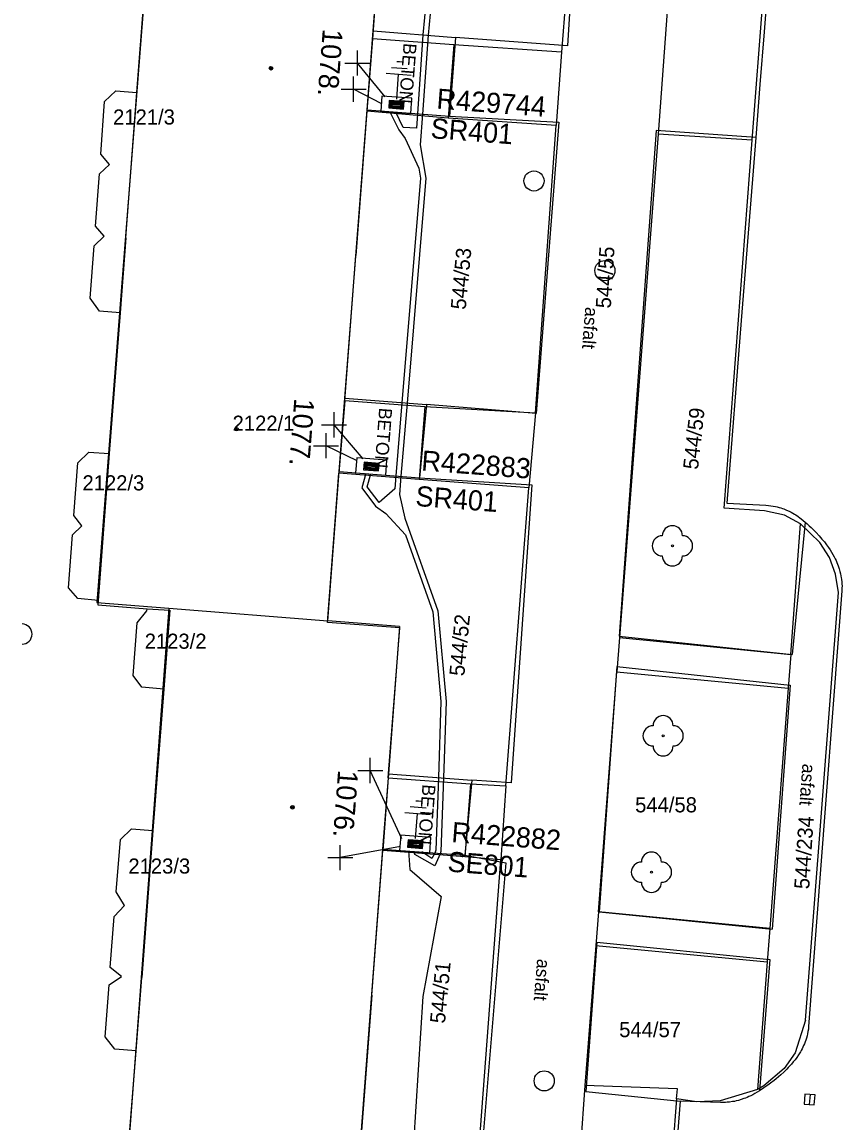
# Model space of a CAD drawing. Extents: x -540150 to -533593, y -1185082 to -1180066.
# Drawn here: x -536258 to -536217.3, y -1184423.9 to -1184369.3 of the extents above; entities that cross this region are included whole.
import ezdxf

# ---------------------------------------------------------------- set-up
doc = ezdxf.new("R2010")
doc.units = 0
for name, color, linetype in [('KN_HRAN_PARCEL', 7, 'Continuous'), ('KN_PARC_Č', 7, 'Continuous'), ('KN_VKP_HRAN_', 7, 'Continuous'), ('Vrstva 1', 7, 'Continuous'), ('Vrstva 10', 7, 'Continuous'), ('Vrstva 11', 7, 'Continuous'), ('Vrstva 14', 7, 'Continuous'), ('Vrstva 15', 7, 'Continuous'), ('Vrstva 22', 7, 'Continuous'), ('Vrstva 27', 7, 'Continuous'), ('Vrstva 28', 7, 'Continuous'), ('Vrstva 29', 7, 'Continuous'), ('Vrstva 30', 7, 'Continuous'), ('Vrstva 34', 7, 'Continuous'), ('Vrstva 39', 7, 'Continuous'), ('Vrstva 40', 7, 'Continuous'), ('Vrstva 47', 7, 'Continuous'), ('Vrstva 5', 7, 'Continuous'), ('Vrstva 59', 7, 'Continuous'), ('Vrstva 8', 7, 'Continuous')]:
    doc.layers.add(name, color=color, linetype=linetype)

# ---------------------------------------------------------------- blocks, each defined once
blk = doc.blocks.new('NN800')
at = {"layer": 'Vrstva 1'}
for points in [[(-0.442, 0.442), (0.442, -0.442)], [(-0.442, -0.442), (0.442, 0.442)]]:
    blk.add_lwpolyline(points, dxfattribs=at)
blk = doc.blocks.new('NN620')
at = {"layer": 'Vrstva 8'}
for points in [[(0.752, 0.004), (-0.748, 0.004)], [(-0.748, 0.004), (-0.748, -0.746)], [(0.752, -0.746), (0.752, 0.004)], [(0.368, -0.18), (-0.376, -0.18)], [(-0.376, -0.18), (-0.376, -0.558)], [(0.321, -0.227), (-0.329, -0.227)], [(-0.329, -0.227), (-0.329, -0.51)], [(-0.329, -0.51), (0.321, -0.51)], [(0.274, -0.274), (-0.281, -0.274)], [(-0.281, -0.274), (-0.281, -0.463)], [(-0.281, -0.463), (0.274, -0.463)], [(0.227, -0.321), (-0.234, -0.321)], [(-0.234, -0.321), (-0.234, -0.416)], [(-0.234, -0.416), (0.227, -0.416)], [(-0.193, -0.369), (0.185, -0.369)], [(0.227, -0.416), (0.227, -0.321)], [(0.274, -0.463), (0.274, -0.274)], [(0.321, -0.51), (0.321, -0.227)], [(0.368, -0.558), (0.368, -0.18)], [(-0.748, -0.746), (0.752, -0.746)], [(-0.376, -0.558), (0.368, -0.558)]]:
    blk.add_lwpolyline(points, dxfattribs=at)
blk = doc.blocks.new('NN810')
at = {"layer": 'Vrstva 14'}
for points in [[(0.004, -0.64), (0.004, -1.89)], [(0.629, -1.89), (-0.621, -1.89)], [(0.388, -2.2), (-0.399, -2.2)], [(0.004, -2.515), (-0.124, -2.515)], [(0.137, -2.515), (0.004, -2.515)]]:
    blk.add_lwpolyline(points, dxfattribs=at)

msp = doc.modelspace()

# ---------------------------------------------------------------- linework, layer by layer
at = {"layer": 'KN_HRAN_PARCEL'}
for p, q in [((-536230.131, -1184356.565), (-536231.231, -1184370.805)), ((-536240.071, -1184362.975), (-536240.621, -1184370.155)), ((-536252.311, -1184372.815), (-536251.771, -1184365.815)), ((-536221.771, -1184375.185), (-536221.221, -1184367.975)), ((-536236.581, -1184370.445), (-536240.621, -1184370.155)), ((-536231.231, -1184370.805), (-536236.581, -1184370.445)), ((-536231.231, -1184370.805), (-536231.501, -1184374.445)), ((-536253.911, -1184373.255), (-536253.361, -1184372.735)), ((-536253.361, -1184372.735), (-536252.311, -1184372.815)), ((-536252.861, -1184380.025), (-536252.311, -1184372.815)), ((-536254.101, -1184375.875), (-536253.911, -1184373.255)), ((-536240.891, -1184373.745), (-536241.441, -1184380.905)), ((-536236.861, -1184374.085), (-536240.891, -1184373.745)), ((-536231.501, -1184374.445), (-536236.861, -1184374.085)), ((-536232.521, -1184388.715), (-536231.501, -1184374.445)), ((-536226.441, -1184374.875), (-536228.361, -1184399.865)), ((-536221.771, -1184375.185), (-536226.441, -1184374.875)), ((-536223.161, -1184393.445), (-536221.771, -1184375.185)), ((-536253.661, -1184376.385), (-536254.101, -1184375.875)), ((-536254.361, -1184379.455), (-536254.161, -1184376.845)), ((-536254.161, -1184376.845), (-536253.661, -1184376.385)), ((-536253.941, -1184379.945), (-536254.361, -1184379.455)), ((-536254.431, -1184380.425), (-536253.941, -1184379.945)), ((-536252.861, -1184380.025), (-536253.141, -1184383.745)), ((-536254.631, -1184383.025), (-536254.431, -1184380.425)), ((-536241.991, -1184388.105), (-536241.441, -1184380.905)), ((-536254.171, -1184383.665), (-536254.631, -1184383.025)), ((-536253.141, -1184383.745), (-536254.171, -1184383.665)), ((-536253.141, -1184383.745), (-536253.681, -1184390.735)), ((-536241.991, -1184388.105), (-536238.011, -1184388.405)), ((-536238.011, -1184388.405), (-536232.521, -1184388.715)), ((-536232.521, -1184388.715), (-536232.861, -1184392.445)), ((-536255.241, -1184391.195), (-536254.701, -1184390.665)), ((-536254.701, -1184390.665), (-536253.681, -1184390.735)), ((-536253.681, -1184390.735), (-536254.231, -1184398.025)), ((-536255.441, -1184393.815), (-536255.241, -1184391.195)), ((-536242.841, -1184399.125), (-536242.281, -1184391.715)), ((-536238.291, -1184392.025), (-536242.281, -1184391.715)), ((-536232.861, -1184392.445), (-536238.291, -1184392.025)), ((-536233.991, -1184407.225), (-536232.861, -1184392.445)), ((-536221.161, -1184393.575), (-536223.161, -1184393.445)), ((-536220.161, -1184393.795), (-536221.161, -1184393.575)), ((-536255.511, -1184394.775), (-536255.041, -1184394.315)), ((-536255.041, -1184394.315), (-536255.441, -1184393.815)), ((-536219.371, -1184394.225), (-536220.161, -1184393.795)), ((-536219.861, -1184400.715), (-536219.371, -1184394.225)), ((-536218.411, -1184395.145), (-536219.371, -1184394.225)), ((-536255.711, -1184397.395), (-536255.511, -1184394.775)), ((-536217.941, -1184395.895), (-536218.411, -1184395.145)), ((-536217.641, -1184396.715), (-536217.941, -1184395.895)), ((-536217.481, -1184397.625), (-536217.641, -1184396.715)), ((-536255.241, -1184397.935), (-536255.711, -1184397.395)), ((-536254.231, -1184398.025), (-536255.241, -1184397.935)), ((-536254.231, -1184398.025), (-536254.251, -1184398.245)), ((-536219.121, -1184418.855), (-536217.481, -1184397.625)), ((-536254.251, -1184398.245), (-536251.801, -1184398.435)), ((-536252.291, -1184399.135), (-536251.811, -1184398.545)), ((-536251.811, -1184398.545), (-536251.801, -1184398.435)), ((-536251.801, -1184398.435), (-536250.671, -1184398.515)), ((-536250.671, -1184398.515), (-536250.971, -1184402.425)), ((-536252.501, -1184401.745), (-536252.291, -1184399.135)), ((-536239.251, -1184399.385), (-536242.841, -1184399.125)), ((-536239.831, -1184406.825), (-536239.251, -1184399.385)), ((-536228.361, -1184399.865), (-536228.491, -1184401.565)), ((-536228.361, -1184399.865), (-536219.861, -1184400.715)), ((-536252.061, -1184402.335), (-536252.501, -1184401.745)), ((-536229.401, -1184413.475), (-536228.491, -1184401.565)), ((-536228.491, -1184401.565), (-536219.991, -1184402.385)), ((-536250.971, -1184402.425), (-536252.061, -1184402.335)), ((-536250.971, -1184402.425), (-536251.511, -1184409.445)), ((-536219.991, -1184402.385), (-536220.891, -1184414.315)), ((-536239.831, -1184406.825), (-536235.751, -1184407.135)), ((-536235.751, -1184407.135), (-536233.991, -1184407.225)), ((-536233.991, -1184407.225), (-536234.241, -1184410.895)), ((-536253.121, -1184409.885), (-536252.581, -1184409.365)), ((-536252.581, -1184409.365), (-536251.511, -1184409.445)), ((-536251.511, -1184409.445), (-536252.071, -1184416.745)), ((-536253.331, -1184412.495), (-536253.121, -1184409.885)), ((-536240.651, -1184417.615), (-536240.101, -1184410.445)), ((-536236.031, -1184410.755), (-536240.101, -1184410.445)), ((-536234.241, -1184410.895), (-536236.031, -1184410.755)), ((-536235.331, -1184425.325), (-536234.241, -1184410.895)), ((-536252.931, -1184413.165), (-536253.331, -1184412.495)), ((-536253.441, -1184413.715), (-536252.931, -1184413.165)), ((-536253.641, -1184416.245), (-536253.441, -1184413.715)), ((-536229.401, -1184413.475), (-536229.531, -1184415.155)), ((-536220.891, -1184414.315), (-536229.401, -1184413.475)), ((-536229.531, -1184415.155), (-536230.071, -1184422.105)), ((-536229.531, -1184415.155), (-536221.021, -1184415.965)), ((-536221.021, -1184415.965), (-536221.501, -1184422.295)), ((-536253.681, -1184417.105), (-536253.081, -1184416.695)), ((-536253.081, -1184416.695), (-536253.641, -1184416.245)), ((-536253.881, -1184419.685), (-536253.681, -1184417.105)), ((-536252.351, -1184420.375), (-536252.071, -1184416.745)), ((-536240.651, -1184417.615), (-536241.201, -1184424.785)), ((-536219.121, -1184418.855), (-536219.641, -1184420.485)), ((-536253.411, -1184420.295), (-536253.881, -1184419.685)), ((-536252.351, -1184420.375), (-536253.411, -1184420.295)), ((-536252.891, -1184427.385), (-536252.351, -1184420.375)), ((-536219.641, -1184420.485), (-536220.181, -1184421.255)), ((-536220.181, -1184421.255), (-536221.191, -1184422.125)), ((-536225.481, -1184422.275), (-536230.071, -1184422.105)), ((-536221.191, -1184422.125), (-536221.501, -1184422.295)), ((-536225.521, -1184422.765), (-536225.481, -1184422.275)), ((-536221.501, -1184422.295), (-536223.361, -1184422.865)), ((-536225.521, -1184422.765), (-536226.051, -1184429.665)), ((-536224.511, -1184422.905), (-536225.521, -1184422.765)), ((-536223.361, -1184422.865), (-536224.511, -1184422.905))]:
    msp.add_line(p, q, dxfattribs=at)
at = {"layer": 'KN_VKP_HRAN_'}
for p, q in [((-536225.911, -1184367.585), (-536226.441, -1184374.875)), ((-536240.621, -1184370.155), (-536240.891, -1184373.745)), ((-536236.581, -1184370.445), (-536236.861, -1184374.085)), ((-536241.991, -1184388.105), (-536242.281, -1184391.715)), ((-536238.011, -1184388.405), (-536238.291, -1184392.025)), ((-536219.861, -1184400.715), (-536219.991, -1184402.385)), ((-536239.831, -1184406.825), (-536240.101, -1184410.445)), ((-536235.751, -1184407.135), (-536236.031, -1184410.755)), ((-536220.891, -1184414.315), (-536221.021, -1184415.965)), ((-536230.071, -1184422.105), (-536230.591, -1184429.345))]:
    msp.add_line(p, q, dxfattribs=at)
at = {"layer": 'Vrstva 10'}
for p, q in [((-536221.385, -1184372.424), (-536221.591, -1184375.045)), ((-536221.591, -1184375.045), (-536222.311, -1184384.125)), ((-536222.311, -1184384.125), (-536223.031, -1184393.205)), ((-536217.321, -1184397.545), (-536217.733, -1184402.953)), ((-536217.733, -1184402.953), (-536218.146, -1184408.36)), ((-536218.146, -1184408.36), (-536218.559, -1184413.767)), ((-536218.559, -1184413.767), (-536218.971, -1184419.175))]:
    msp.add_line(p, q, dxfattribs=at)
for points in [[(-536220.731, -1184363.755), (-536220.891, -1184365.905), (-536221.051, -1184368.055), (-536221.183, -1184369.803), (-536221.385, -1184372.424)], [(-536223.031, -1184393.205), (-536222.061, -1184393.255), (-536221.091, -1184393.305), (-536220.96, -1184393.314), (-536220.838, -1184393.328), (-536220.725, -1184393.345), (-536220.62, -1184393.365), (-536220.523, -1184393.387), (-536220.432, -1184393.41), (-536220.348, -1184393.435), (-536220.269, -1184393.461), (-536220.196, -1184393.487), (-536220.06, -1184393.541), (-536219.942, -1184393.595), (-536219.84, -1184393.647), (-536219.751, -1184393.696), (-536219.673, -1184393.741), (-536219.606, -1184393.783), (-536219.489, -1184393.862), (-536219.401, -1184393.924), (-536219.336, -1184393.974), (-536219.238, -1184394.052), (-536219.141, -1184394.135), (-536219.038, -1184394.227), (-536218.939, -1184394.317), (-536218.846, -1184394.406), (-536218.757, -1184394.492), (-536218.59, -1184394.661), (-536218.441, -1184394.823), (-536218.307, -1184394.977), (-536218.188, -1184395.123), (-536218.081, -1184395.262), (-536217.987, -1184395.394), (-536217.903, -1184395.519), (-536217.828, -1184395.638), (-536217.763, -1184395.75), (-536217.705, -1184395.856), (-536217.653, -1184395.956), (-536217.608, -1184396.05), (-536217.569, -1184396.139), (-536217.534, -1184396.223), (-536217.504, -1184396.303), (-536217.452, -1184396.453), (-536217.413, -1184396.585), (-536217.384, -1184396.702), (-536217.363, -1184396.805), (-536217.347, -1184396.896), (-536217.336, -1184396.976), (-536217.321, -1184397.116), (-536217.315, -1184397.222), (-536217.313, -1184397.303), (-536217.314, -1184397.423), (-536217.321, -1184397.545)], [(-536218.971, -1184419.175), (-536218.983, -1184419.299), (-536219.001, -1184419.418), (-536219.023, -1184419.532), (-536219.048, -1184419.641), (-536219.077, -1184419.745), (-536219.109, -1184419.844), (-536219.143, -1184419.94), (-536219.179, -1184420.031), (-536219.217, -1184420.119), (-536219.257, -1184420.203), (-536219.297, -1184420.283), (-536219.339, -1184420.36), (-536219.381, -1184420.434), (-536219.468, -1184420.575), (-536219.557, -1184420.705), (-536219.644, -1184420.824), (-536219.731, -1184420.934), (-536219.816, -1184421.036), (-536219.899, -1184421.13), (-536219.98, -1184421.216), (-536220.057, -1184421.296), (-536220.208, -1184421.443), (-536220.345, -1184421.568), (-536220.469, -1184421.676), (-536220.58, -1184421.768), (-536220.679, -1184421.847), (-536220.856, -1184421.983), (-536220.992, -1184422.081), (-536221.199, -1184422.226), (-536221.411, -1184422.365), (-536221.529, -1184422.438), (-536221.64, -1184422.503), (-536221.744, -1184422.559), (-536221.842, -1184422.609), (-536221.934, -1184422.652), (-536222.02, -1184422.69), (-536222.102, -1184422.723), (-536222.178, -1184422.753), (-536222.321, -1184422.802), (-536222.448, -1184422.839), (-536222.559, -1184422.867), (-536222.656, -1184422.889), (-536222.742, -1184422.904), (-536222.892, -1184422.926)], [(-536225.341, -1184422.875), (-536225.611, -1184426.225), (-536225.881, -1184429.575), (-536226.04, -1184431.537)], [(-536222.892, -1184422.926), (-536223.006, -1184422.937), (-536223.092, -1184422.943), (-536223.221, -1184422.947), (-536223.351, -1184422.945), (-536224.346, -1184422.91), (-536225.341, -1184422.875)]]:
    msp.add_lwpolyline(points, dxfattribs=at)
at = {"layer": 'Vrstva 11'}
for p, q in [((-536230.001, -1184356.385), (-536230.941, -1184370.505)), ((-536240.582, -1184369.762), (-536236.489, -1184370.077)), ((-536236.489, -1184370.077), (-536236.791, -1184373.995)), ((-536230.941, -1184370.505), (-536236.489, -1184370.077)), ((-536240.884, -1184373.68), (-536236.791, -1184373.995)), ((-536236.791, -1184373.995), (-536231.371, -1184374.295)), ((-536231.371, -1184374.295), (-536232.491, -1184388.745)), ((-536226.531, -1184374.695), (-536228.37, -1184399.801)), ((-536221.591, -1184375.045), (-536226.531, -1184374.695)), ((-536241.987, -1184387.992), (-536237.931, -1184388.305)), ((-536237.931, -1184388.305), (-536238.281, -1184391.935)), ((-536232.491, -1184388.745), (-536237.931, -1184388.305)), ((-536242.268, -1184391.628), (-536238.281, -1184391.935)), ((-536238.281, -1184391.935), (-536232.711, -1184392.285)), ((-536232.711, -1184392.285), (-536233.728, -1184407.08)), ((-536219.141, -1184394.135), (-536219.791, -1184400.715)), ((-536228.37, -1184399.801), (-536219.791, -1184400.715)), ((-536228.481, -1184401.31), (-536229.372, -1184413.483)), ((-536228.481, -1184401.31), (-536219.891, -1184402.225)), ((-536219.891, -1184402.225), (-536220.771, -1184414.345)), ((-536239.828, -1184406.629), (-536235.691, -1184406.945)), ((-536235.691, -1184406.945), (-536236.031, -1184410.675)), ((-536233.728, -1184407.08), (-536235.691, -1184406.945)), ((-536240.113, -1184410.364), (-536236.031, -1184410.675)), ((-536236.031, -1184410.675), (-536234.001, -1184411.055)), ((-536234.001, -1184411.055), (-536235.191, -1184425.275)), ((-536229.372, -1184413.483), (-536220.771, -1184414.345)), ((-536229.482, -1184414.984), (-536230.026, -1184422.405)), ((-536229.482, -1184414.984), (-536220.891, -1184415.845)), ((-536220.891, -1184415.845), (-536221.411, -1184422.365)), ((-536230.026, -1184422.405), (-536225.341, -1184422.875))]:
    msp.add_line(p, q, dxfattribs=at)
at = {"layer": 'Vrstva 22'}
for centre in [(-536225.731, -1184395.315), (-536226.191, -1184404.745), (-536226.771, -1184411.515)]:
    msp.add_circle(centre, 0.05, dxfattribs=at)
for centre, start, end in [((-536225.731, -1184394.815), 0, 180), ((-536226.231, -1184395.315), 90, 270), ((-536225.231, -1184395.315), 270, 90), ((-536225.731, -1184395.815), 180, 0), ((-536258.011, -1184399.695), 270, 90), ((-536226.191, -1184404.245), 0, 180), ((-536226.691, -1184404.745), 90, 270), ((-536225.691, -1184404.745), 270, 90), ((-536226.191, -1184405.245), 180, 0), ((-536226.771, -1184411.015), 0, 180), ((-536227.271, -1184411.515), 90, 270), ((-536226.271, -1184411.515), 270, 90), ((-536226.771, -1184412.015), 180, 0)]:
    msp.add_arc(centre, 0.5, start, end, dxfattribs=at)
at = {"layer": 'Vrstva 27'}
msp.add_line((-536218.901, -1184422.546), (-536218.941, -1184423.044), dxfattribs=at)
msp.add_lwpolyline([(-536219.15, -1184422.525), (-536219.191, -1184423.024), (-536218.692, -1184423.065), (-536218.651, -1184422.566)], close=True, dxfattribs=at)
for centre in [(-536232.601, -1184377.205), (-536229.081, -1184381.655), (-536232.091, -1184421.875)]:
    msp.add_circle(centre, 0.5, dxfattribs=at)
at = {"layer": 'Vrstva 39'}
for centre, radius in [((-536245.655, -1184371.612), 0.09), ((-536245.655, -1184371.612), 0.0398), ((-536247.36, -1184389.525), 0.09), ((-536247.36, -1184389.525), 0.0398), ((-536244.589, -1184408.291), 0.09), ((-536244.589, -1184408.291), 0.0398)]:
    msp.add_circle(centre, radius, dxfattribs=at)
at = {"layer": 'Vrstva 5'}
for p, q in [((-536250.051, -1184343.825), (-536254.291, -1184398.135)), ((-536254.291, -1184398.135), (-536250.722, -1184398.417)), ((-536250.722, -1184398.417), (-536254.811, -1184452.825)), ((-536250.722, -1184398.417), (-536242.839, -1184399.042)), ((-536239.271, -1184399.325), (-536242.839, -1184399.042))]:
    msp.add_line(p, q, dxfattribs=at)
for points in [[(-536242.839, -1184399.042), (-536242.268, -1184391.628), (-536241.987, -1184387.992), (-536240.884, -1184373.68), (-536240.582, -1184369.762), (-536239.506, -1184355.799), (-536239.224, -1184352.139), (-536238.651, -1184344.705)], [(-536238.176, -1184355.901), (-536238.231, -1184357.046), (-536237.959, -1184357.134), (-536237.341, -1184357.205), (-536237.441, -1184358.055), (-536237.207, -1184359.922), (-536237.456, -1184363.054), (-536238.11, -1184369.952), (-536238.386, -1184373.872), (-536238.433, -1184374.588), (-536239.088, -1184374.555), (-536239.458, -1184373.79)], [(-536237.206, -1184363.076), (-536237.86, -1184369.972), (-536238.137, -1184373.891), (-536238.242, -1184375.408), (-536237.976, -1184377.065), (-536238.903, -1184388.23), (-536239.205, -1184391.864), (-536239.275, -1184392.776), (-536239.005, -1184393.943), (-536237.368, -1184398.538), (-536236.966, -1184403.042), (-536237.094, -1184406.838), (-536237.217, -1184410.484), (-536237.259, -1184410.597), (-536237.523, -1184411.203), (-536238.521, -1184410.639), (-536238.52, -1184410.485)], [(-536239.747, -1184373.768), (-536239.311, -1184374.666), (-536238.991, -1184375.09), (-536238.319, -1184376.577), (-536238.226, -1184377.065), (-536239.152, -1184388.211), (-536239.453, -1184391.845), (-536239.509, -1184392.48), (-536240.285, -1184393.171), (-536240.874, -1184392.38), (-536240.7, -1184391.749)], [(-536240.953, -1184391.729), (-536241.148, -1184392.43), (-536240.473, -1184393.34), (-536239.957, -1184393.713), (-536238.978, -1184394.77), (-536237.614, -1184398.592), (-536237.216, -1184403.048), (-536237.344, -1184406.819), (-536237.465, -1184410.426), (-536237.517, -1184410.566), (-536237.666, -1184410.834), (-536238.166, -1184410.512)], [(-536239.271, -1184399.325), (-536239.828, -1184406.629), (-536240.113, -1184410.364), (-536241.211, -1184424.762), (-536241.487, -1184428.373), (-536242.586, -1184442.793)], [(-536238.828, -1184410.462), (-536238.761, -1184411.375), (-536237.201, -1184412.715), (-536238.111, -1184417.685), (-536238.577, -1184424.963), (-536238.761, -1184427.845), (-536238.833, -1184428.576), (-536238.851, -1184428.755), (-536239.648, -1184428.594), (-536239.674, -1184428.511)]]:
    msp.add_lwpolyline(points, dxfattribs=at)
at = {"layer": 'Vrstva 59'}
for points in [[(-536239.991, -1184373.023), (-536241.356, -1184371.351)], [(-536240.158, -1184373.372), (-536241.551, -1184372.647)], [(-536241.083, -1184390.996), (-536242.526, -1184389.312)], [(-536241.38, -1184391.095), (-536242.922, -1184390.345)], [(-536239.16, -1184409.857), (-536240.723, -1184406.468)], [(-536239.219, -1184410.237), (-536242.213, -1184410.792)]]:
    msp.add_lwpolyline(points, dxfattribs=at)

# ---------------------------------------------------------------- block references
at = {"layer": 'Vrstva 15'}
for p, rotation in [((-536239.459, -1184373.79), 175.64315828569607), ((-536238.521, -1184410.485), 175.64315842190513)]:
    msp.add_blockref('NN810', p, dxfattribs=dict(at, rotation=rotation))
at = {"layer": 'Vrstva 28'}
for p, rotation in [((-536239.459, -1184373.79), 175.65466110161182), ((-536240.701, -1184391.749), 175.65466110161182), ((-536238.521, -1184410.485), 175.6546611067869)]:
    msp.add_blockref('NN620', p, dxfattribs=dict(at, rotation=rotation))
at = {"layer": 'Vrstva 34'}
for p, rotation in [((-536241.356, -1184371.352), 45), ((-536241.551, -1184372.648), 45), ((-536242.526, -1184389.313), 44.99999995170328), ((-536242.922, -1184390.346), 45), ((-536240.723, -1184406.469), 45), ((-536242.213, -1184410.793), 45)]:
    msp.add_blockref('NN800', p, dxfattribs=dict(at, rotation=rotation))

# ---------------------------------------------------------------- texts
at = {"layer": 'KN_PARC_Č'}
for s, p in [('2121/3', (-536253.491, -1184374.405)), ('2122/1', (-536247.56, -1184389.605)), ('2122/3', (-536255.011, -1184392.565)), ('2123/2', (-536251.921, -1184400.425)), ('544/58', (-536227.581, -1184408.545)), ('2123/3', (-536252.731, -1184411.585)), ('544/57', (-536228.371, -1184419.705))]:
    msp.add_text(s, height=0.75, dxfattribs=at).set_placement(p)
for s, rotation, p in [('544/53', 84.6, (-536235.991, -1184383.615)), ('544/55', 86.4, (-536228.791, -1184383.545)), ('544/59', 83.7, (-536224.461, -1184391.555)), ('544/52', 84.6, (-536236.061, -1184401.805)), ('544/234', 86.4, (-536218.941, -1184412.375)), ('544/51', 84.6, (-536237.021, -1184419.045))]:
    msp.add_text(s, height=0.75, rotation=rotation, dxfattribs=at).set_placement(p)
at = {"layer": 'Vrstva 29'}
for s, p in [('R429744', (-536237.461, -1184373.613)), ('R422883', (-536238.215, -1184391.573)), ('R422882', (-536236.719, -1184410.016))]:
    msp.add_text(s, height=1, rotation=355.655, dxfattribs=at).set_placement(p)
at = {"layer": 'Vrstva 30'}
for s, p in [('SR401', (-536237.754, -1184375.078)), ('SR401', (-536238.508, -1184393.332)), ('SE801', (-536236.914, -1184411.481))]:
    msp.add_text(s, height=1, rotation=355.655, dxfattribs=at).set_placement(p)
at = {"layer": 'Vrstva 40'}
for s, rotation, p in [('BETON', 265.5927, (-536239.07, -1184370.346)), ('asfalt', 265.5679, (-536230.054, -1184383.447)), ('BETON', 265.5927, (-536240.283, -1184388.449)), ('asfalt', 265.6378, (-536219.273, -1184406.117)), ('BETON', 265.6383, (-536238.13, -1184407.138)), ('asfalt', 265.2164, (-536232.439, -1184415.801))]:
    msp.add_text(s, height=0.65, rotation=rotation, dxfattribs=at).set_placement(p)
at = {"layer": 'Vrstva 47'}
for s, rotation, p in [('1078.', 265.5927, (-536243.08, -1184369.636)), ('1077.', 265.5927, (-536244.493, -1184387.978)), ('1076.', 265.6383, (-536242.32, -1184406.425))]:
    msp.add_text(s, height=1, rotation=rotation, dxfattribs=at).set_placement(p)

doc.saveas('drawing.dxf')
